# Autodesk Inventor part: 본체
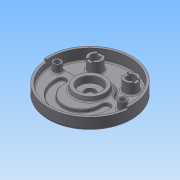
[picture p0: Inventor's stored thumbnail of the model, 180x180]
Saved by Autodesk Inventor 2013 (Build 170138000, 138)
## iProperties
Created: 2015-04
Part Number: 본체
Material: 일반
Document SubType Name: Modeling
Designer: Administrator
Density: 1 g/cm^3
Author: Administrator
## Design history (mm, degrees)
sketch "스케치1"
  geometry: C1 r 95 at (0, 0); 1 further point
  constraints: 1 centre point, 1 coincident
  dimensions: "d0" = 190 diameter of C1
extrude "돌출1" new body sketch "스케치1" distance "d1" = 32; taper "d2" = 0 deg
sketch "스케치2"
  geometry: C1 r 95 at (0, 0) reference; C2 r 90 at (0, 0)
  constraints: 1 centre point, 1 coincident
  dimensions: "d3" = 180 diameter of C2
extrude "돌출2" cut sketch "스케치2" distance "d4" = 25; taper "d5" = 0 deg
sketch "스케치4"
  geometry: C1 r 90 at (0, 0) reference; C2 r 15 at (-40, 52)
  constraints: 1 centre point
  dimensions: "d8" = 30 diameter of C2; "d9" = 52 vertical distance of C1.centre C2.centre; "d10" = 40 horizontal distance of C1.centre C2.centre
extrude "돌출3" join sketch "스케치4" distance "d11" = 25; taper "d12" = 0 deg
sketch "스케치5"
  geometry: C1 r 15 at (0, 0) reference; C2 r 10 at (0, 0); 1 further point
  constraints: 1 centre point, 1 coincident
  dimensions: "d13" = 20 diameter of C2
extrude "돌출4" cut sketch "스케치5" stored distance "d14" = 18; taper "d15" = 0 deg
sketch "스케치6"
  geometry: L1 (-6, 13.748)-(-6, -13.748); L2 (6, 13.748)-(6, -13.748); C1 r 10 at (0, 0) reference; A1 r 15 centre (0, 0) between (-6, 13.748) and (-6, -13.748) reference; 1 further point
  constraints: 4 end point, 4 point on circle, 1 parallel, 1 vertical
  dimensions: "d16" = 6 distance from line of C1.centre L1; "d17" = 6 distance from line of L2 C1.centre
extrude "돌출5" cut sketch "스케치6" distance "d18" = 3; taper "d19" = 0 deg
sketch "스케치7"
  geometry: C1 r 90 at (0, 0) reference; C2 r 15 at (40, 52)
  constraints: 1 centre point
  dimensions: "d20" = 30 diameter of C2; "d21" = 40 horizontal distance of C1.centre C2.centre; "d22" = 52 vertical distance of C1.centre C2.centre
extrude "돌출6" join sketch "스케치7" distance "d23" = 25; taper "d24" = 0 deg
sketch "스케치9"
  geometry: C1 r 15 at (0, 0) reference; C2 r 10 at (0, 0); 1 further point
  constraints: 1 centre point, 1 coincident
  dimensions: "d30" = 20 diameter of C2
extrude "돌출8" cut sketch "스케치9" stored distance "d31" = 3; taper "d32" = 0 deg
sketch "스케치8"
  geometry: L1 (-13.748, -6)-(13.748, -6); L2 (-13.748, 6)-(13.748, 6); A1 r 15 centre (0, 0) between (-13.748, -6) and (13.748, -6) reference; 1 further point
  constraints: 4 end point, 4 point on circle, 1 horizontal, 1 parallel
  dimensions: "d25" = 6 distance from line of A1.centre L1; "d27" = 6 distance from line of L2 A1.centre
extrude "돌출7" cut sketch "스케치8" distance "d28" = 3; taper "d29" = 0 deg
sketch "스케치10"
  geometry: L1 (-76.916, 12)-(-47.117, 12); L2 (47.117, 12)-(76.916, 12); C1 r 90 at (0, 0) reference; A1 r 90 centre (0, 0) between (-86.53, 24.75) and (86.53, 24.75); A2 r 42 centre (0, 0) between (38.056, 17.769) and (-38.056, 17.769); A3 r 10 centre (-47.117, 22) between (-47.117, 12) and (-38.056, 17.769); A4 r 10 centre (-76.916, 22) between (-86.53, 24.75) and (-76.916, 12); A5 r 90 centre (0, 0) between (-86.53, 24.75) and (86.53, 24.75) reference; A6 r 10 centre (47.117, 22) between (38.056, 17.769) and (47.117, 12); A7 r 10 centre (76.916, 22) between (76.916, 12) and (86.53, 24.75)
  constraints: 14 point on circle, 12 tangent, 6 centre point, 4 end point, 2 coincident, 2 horizontal, 1 concentric
  dimensions: "d34" = 84 diameter of A2; "d36" = 20 diameter of A3; "d37" = 20 diameter of A4; "d38" = 20 diameter of A6; "d39" = 20 diameter of A7; "d40" = 29.79866 distance of L1.start L1.end
extrude "돌출9" join sketch "스케치10" distance "d41" = 7; taper "d42" = 0 deg
sketch "스케치11"
  geometry: C1 r 35 at (0, 0); A1 r 90 centre (0, 0) between (-86.53, 24.75) and (86.53, 24.75) reference
  constraints: 1 centre point, 1 coincident
  dimensions: "d43" = 70 diameter of C1
extrude "돌출10" join sketch "스케치11" distance "d44" = 10; taper "d45" = -10 deg
sketch "스케치12"
  geometry: C1 r 33.237 at (0, 0) reference; C2 r 25 at (0, 0)
  constraints: 1 centre point, 1 coincident
  dimensions: "d46" = 50 diameter of C2
extrude "돌출11" cut sketch "스케치12" distance "d47" = 15; taper "d48" = 0 deg
sketch "스케치13"
  geometry: C1 r 25 at (0, 0) reference; C2 r 11.5 at (0, 0)
  constraints: 1 centre point, 1 coincident
  dimensions: "d49" = 23 diameter of C2
extrude "돌출12" cut sketch "스케치13" stored distance "d50" = 15; taper "d51" = 0 deg
sketch "스케치14"
  geometry: L1 (-76.916, 12)-(-47.117, 12) reference; L2 (47.117, 12)-(76.916, 12) reference; L3 (-76.916, 12)-(-47.117, 12) reference; L4 (47.117, 12)-(76.916, 12) reference; L5 (-59, -14)-(-59, -19); L6 (-41, -14)-(-41, -19); L7 (41, -14)-(41, -19); L8 (59, -14)-(59, -19); C1 r 35 at (0, 0) reference; C2 r 25 at (0, 0) reference; C3 r 35 at (0, 0) reference; C4 r 10 at (40, 52) reference; C5 r 15 at (40, 52) reference; C6 r 10 at (-40, 52) reference; C7 r 15 at (-40, 52) reference; C8 r 95 at (0, 0) reference; C9 r 25 at (0, 0) reference; C10 r 35 at (0, 0) reference; C11 r 10 at (40, 52) reference; C12 r 15 at (40, 52) reference; C13 r 10 at (-40, 52) reference; C14 r 15 at (-40, 52) reference; C15 r 95 at (0, 0) reference; A1 r 10 centre (76.916, 22) between (76.916, 12) and (86.53, 24.75) reference; A2 r 90 centre (0, 0) between (86.53, 24.75) and (-86.53, 24.75) reference; A3 r 10 centre (-76.916, 22) between (-86.53, 24.75) and (-76.916, 12) reference; A4 r 10 centre (-47.117, 22) between (-47.117, 12) and (-38.056, 17.769) reference; A5 r 42 centre (0, 0) between (38.056, 17.769) and (-38.056, 17.769) reference; A6 r 10 centre (47.117, 22) between (38.056, 17.769) and (47.117, 12) reference; A7 r 90 centre (0, 0) between (-86.53, 24.75) and (86.53, 24.75) reference; A8 r 10 centre (76.916, 22) between (76.916, 12) and (86.53, 24.75) reference; A9 r 90 centre (0, 0) between (86.53, 24.75) and (-86.53, 24.75) reference; A10 r 10 centre (-76.916, 22) between (-86.53, 24.75) and (-76.916, 12) reference; A11 r 10 centre (-47.117, 22) between (-47.117, 12) and (-38.056, 17.769) reference; A12 r 42 centre (0, 0) between (38.056, 17.769) and (-38.056, 17.769) reference; A13 r 10 centre (47.117, 22) between (38.056, 17.769) and (47.117, 12) reference; A14 r 90 centre (0, 0) between (-86.53, 24.75) and (86.53, 24.75) reference; A15 r 9 centre (-50, -14) between (-41, -14) and (-59, -14); A16 r 9 centre (50, -14) between (59, -14) and (41, -14); A17 r 41 centre (0, -19) between (-41, -19) and (41, -19); A18 r 59 centre (0, -19) between (-59, -19) and (59, -19)
  constraints: 8 end point, 8 point on circle, 8 tangent, 4 centre point, 1 coincident, 1 vertical alignment
  dimensions: "d53" = 19 distance of A18.centre C1.centre; "d55" = 18 diameter of A15; "d56" = 14 vertical distance of A15.centre C1.centre; "d57" = 50 horizontal distance of C1.centre A15.centre; "d58" = 18 diameter of A16; "d59" = 14 vertical distance of C1.centre A16.centre; "d60" = 50 horizontal distance of A16.centre C1.centre; "d61" = 59 radius of A18; "d62" = 41 radius of A17
extrude "돌출13" cut sketch "스케치14" distance "d63" = 7; taper "d64" = 0 deg
sketch "스케치15"
  geometry: C1 r 35 at (0, 0) reference; C2 r 9 at (-74, 0); C3 r 9 at (74, 0)
  constraints: 2 centre point, 2 horizontal alignment
  dimensions: "d65" = 18 diameter of C2; "d66" = 18 diameter of C3; "d67" = 74 distance of C1.centre C2.centre; "d68" = 74 distance of C3.centre C1.centre
extrude "돌출14" join sketch "스케치15" stored distance "d69" = 7; taper "d70" = 0 deg
sketch "스케치16"
  geometry: C1 r 9 at (-74, 0) reference; C2 r 9 at (74, 0) reference; 2 further points
  constraints: 2 coincident
hole "구멍1" sketch "스케치16" at (-74, 0), (74, 0) diameter "d71" = 11; stored, may be unused: countersink angle "d75" = 90 deg, drill point angle "d77" = 118 deg; dims "d72" = 6, "d73" = 18, "d74" = 11, "d76" = 8
sketch "스케치17"
  geometry: L1 (0, 0)-(-94.638, -8.28); L2 (0, 0)-(94.638, -8.28); L3 (0, 0)-(42.605, 0); L4 (0, 0)-(-4.864, -0.426); L5 (0, 0)-(-42.623, 0); C1 r 90 at (0, 0) reference; A1 r 95 centre (0, 0) between (-94.638, -8.28) and (94.638, -8.28) reference; A2 r 90 centre (0, 0) between (-89.658, -7.844) and (89.658, -7.844)
  constraints: 10 end point, 4 point on circle, 3 point on line, 2 coincident, 1 centre point, 1 collinear, 1 concentric, 1 horizontal
  dimensions: "d78" = 5 deg angle of L5 L1; "d79" = 5 deg angle of L3 L2
extrude "돌출15" cut sketch "스케치17" distance "d80" = 5; taper "d81" = 0 deg
sketch "스케치18"
  geometry: L1 (0, 0)-(50.912, -50.912); L2 (0, 0)-(0, -81.344); L3 (0, 0)-(-50.912, -50.912); C1 r 95 at (0, 0) reference; C2 r 51 at (0, 0); A1 r 72 centre (0, 0) between (50.912, -50.912) and (-50.912, -50.912)
  constraints: 6 end point, 2 centre point, 2 coincident, 2 point on circle, 1 vertical
  dimensions: "d82" = 51 radius of C2; "d83" = 72 radius of A1; "d84" = 45 deg angle of L1 L2; "d85" = 45 deg angle of L2 L3
extrude "돌출16" join sketch "스케치18" distance "d86" = 5; taper "d87" = 0 deg
sketch "스케치19"
  geometry: C1 r 11.5 at (0, 0); A1 r 11.5 centre (0, 0) between (-8.132, -8.132) and (8.132, -8.132) reference
  constraints: 1 centre point, 1 coincident, 1 concentric
extrude "돌출17" cut sketch "스케치19" stored distance "d88" = 0; taper "d89" = 0 deg
sketch "스케치20"
  geometry: C1 r 51 at (0, 0); A1 r 72 centre (0, 0) between (-50.912, -50.912) and (50.912, -50.912) reference
  constraints: 1 centre point, 1 coincident
  dimensions: "d90" = 51 radius of C1
extrude "돌출18" cut sketch "스케치20" distance "d91" = 5; taper "d92" = 0 deg
fillet "모깎기1" dims "d93" = 5
fillet "모깎기2" dims "d94" = 5
fillet "모깎기3" dims "d95" = 3
sketch "스케치22"
  geometry: C1 r 68 at (0, 0); A1 r 67 centre (0, 0) between (-43.709, -50.78) and (43.709, -50.78) reference
  constraints: 1 centre point, 1 coincident, 1 other
  dimensions: "d98" = 68 radius of C1
feature "엠보싱1" sketch "스케치22" dims "d99" = 0.5, "d100" = 0
fillet "모깎기4" dims "d101" = 5
fillet "모깎기5" dims "d102" = 1
chamfer "모따기1" distance "d103" = 1; stored, may be unused: second distance "d104" = 2, angle "d105" = 45 deg
chamfer "모따기2" distance "d106" = 1; stored, may be unused: second distance "d107" = 2, angle "d108" = 45 deg
fillet "모깎기6" dims "d109" = 3
fillet "모깎기7" dims "d110" = 0.3
node "솔리드1"
node "절단 모서리 투영1"
node "절단 모서리 투영2"
other parameters: "d35" = 12, "d52" = 118, "d54" = 82
